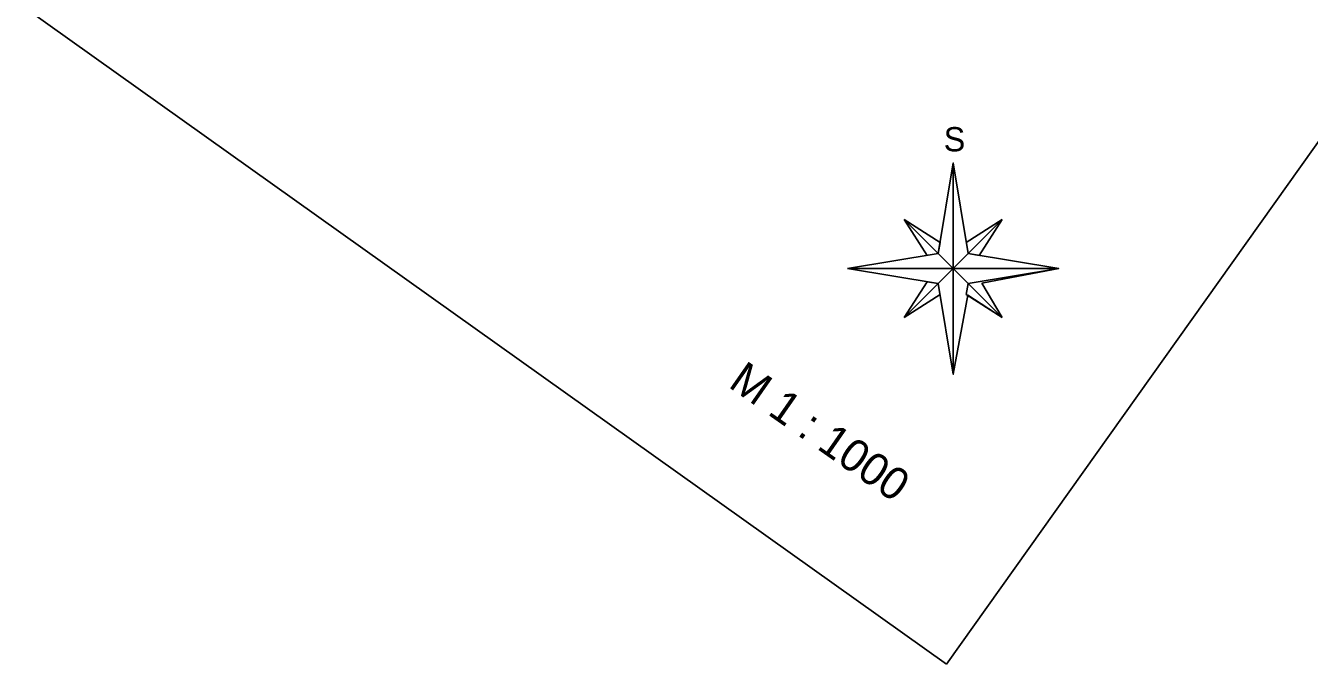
# Model space of a CAD drawing. Extents: x -505028 to -503155, y -1080361 to -1077947.
# Drawn here: x -504654.1 to -504415.6, y -1078990.8 to -1078872.2 of the extents above; entities that cross this region are included whole.
import ezdxf

# ---------------------------------------------------------------- set-up
doc = ezdxf.new("R2010")
doc.units = 0
for name, color, linetype in [('Default', 7, 'Continuous'), ('POPIS', 7, 'Continuous'), ('Vrstva 53', 7, 'Continuous'), ('Vrstva 63', 7, 'Continuous')]:
    doc.layers.add(name, color=color, linetype=linetype)

# ---------------------------------------------------------------- blocks, each defined once
blk = doc.blocks.new('_U19')
at = {"layer": 'Default'}
for p, q in [((-178.7, -629.2), (178.7, 629.2)), ((-63.7, 114.2), (178.7, 629.2)), ((135.6, 146.5), (178.7, 629.2)), ((-34.5, 176.3), (-208.7, 374.2)), ((-208.7, 374.2), (-131.8, 122)), ((-208.7, 374.2), (0, 0)), ((-114.2, -63.7), (-629.2, 178.7)), ((-63.7, 114.2), (-629.2, 178.7)), ((-629.2, 178.7), (629.2, -178.7)), ((374.2, 208.7), (0, 0)), ((135.6, 146.5), (374.2, 208.7)), ((374.2, 208.7), (182.7, 42.1)), ((182.7, 42.1), (629.2, -178.7)), ((-374.2, -208.7), (0, 0)), ((-374.2, -208.7), (-176.3, -34.5)), ((-114.2, -63.7), (-178.7, -629.2)), ((208.7, -374.2), (0, 0)), ((-122, -131.8), (-374.2, -208.7)), ((63.7, -114.2), (-178.7, -629.2)), ((63.7, -114.2), (629.2, -178.7)), ((208.7, -374.2), (131.8, -122)), ((34.5, -176.3), (208.7, -374.2))]:
    blk.add_line(p, q, dxfattribs=at)
for points in [[(0, 0), (114.2, 63.7), (178.7, 629.2)], [(-208.7, 374.2), (-63.7, 114.2), (-34.5, 176.3)], [(0, 0), (-63.7, 114.2), (-629.2, 178.7)], [(374.2, 208.7), (114.2, 63.7), (176.3, 34.5)], [(-374.2, -208.7), (-114.2, -63.7), (-176.3, -34.5)], [(-178.7, -629.2), (0, 0), (-114.2, -63.7)], [(0, 0), (63.7, -114.2), (629.2, -178.7)], [(208.7, -374.2), (63.7, -114.2), (34.5, -176.3)]]:
    blk.add_lwpolyline(points, close=True, dxfattribs=at)
blk.add_text('S', height=150, rotation=74.14529, dxfattribs=at).set_placement((-713.9, 141.5))

msp = doc.modelspace()

# ---------------------------------------------------------------- linework, layer by layer
at = {"layer": 'Vrstva 63'}
msp.add_lwpolyline([(-504483.07, -1078990.76), (-504654.14, -1078868.97), (-504481.9, -1078627.02), (-504310.82, -1078748.81)], close=True, dxfattribs=at)

# ---------------------------------------------------------------- block references
at = {"layer": 'POPIS', "xscale": 0.030000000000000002, "yscale": 0.030000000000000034, "rotation": -74.14528506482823}
msp.add_blockref('_U19', (-504481.82, -1078917.26), dxfattribs=at)

# ---------------------------------------------------------------- texts
at = {"layer": 'Vrstva 53'}
msp.add_text('M 1 : 1000', height=6, rotation=325.1015, dxfattribs=at).set_placement((-504523.8, -1078939.13))

doc.saveas('drawing.dxf')
